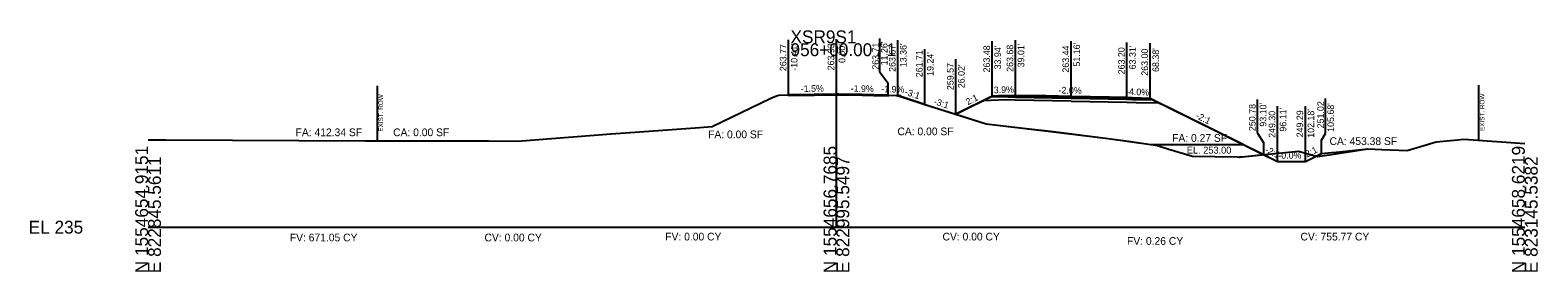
# Model space of a CAD drawing. Extents: x -26 to 823017, y -16 to 1558356.
# Drawn here: x -25.7 to 302.8, y 3990.3 to 4042.8 of the extents above; entities that cross this region are included whole.
import ezdxf

# ---------------------------------------------------------------- set-up
doc = ezdxf.new("R2010")
doc.units = 0
for name, color, linetype in [('ASPHALT_19MM1', 7, 'Continuous'), ('CONST_DCH', 7, 'Continuous'), ('CONST_LV3', 7, 'Continuous'), ('Draft_XS_Grid', 7, 'Continuous'), ('DTM_CORRIDOR', 7, 'Continuous'), ('DTM_P_FINISHED_GRADE2', 7, 'Continuous'), ('DTM_TEMP_DROP', 7, 'Continuous'), ('DTM_X_GROUND', 7, 'Continuous'), ('PROFILES_DCH_2', 7, 'Continuous'), ('XS_CELL', 7, 'Continuous'), ('XS_P_ASPHALT', 7, 'Continuous'), ('XS_P_DR_GRAVEL', 7, 'Continuous'), ('XS_P_GROUND', 7, 'Continuous'), ('XS_P_NULL_POINT', 7, 'Continuous'), ('XS_P_SHOULDER', 7, 'Continuous'), ('XS_P_SUBGRADE_GRANULAR', 7, 'Continuous'), ('XS_P_SUBGRADE_LEVELING', 7, 'Continuous'), ('XS_P_SUBGRADE_MILLING', 7, 'Continuous'), ('XS_P_SUBGRADE_UNDERCUT', 7, 'Continuous'), ('XS_P_TX_CLEARZONE', 7, 'Continuous'), ('XS_P_TX_FS_BS', 7, 'Continuous'), ('XS_SHEET_EW_TX_AREA', 7, 'Continuous'), ('XS_SHEET_EW_TX_VOLUME', 7, 'Continuous'), ('XS_X_ROW', 7, 'Continuous')]:
    doc.layers.add(name, color=color, linetype=linetype)

msp = doc.modelspace()

# ---------------------------------------------------------------- linework, layer by layer
at = {"layer": 'ASPHALT_19MM1'}
msp.add_lwpolyline([(189.01, 4028.31), (201.16, 4028.07), (213.31, 4027.82), (213.31, 4028.03), (201.16, 4028.27), (189.01, 4028.52), (189.01, 4028.31)], dxfattribs=at)
at = {"layer": 'CONST_DCH'}
msp.add_lwpolyline([(189.01, 4028.52), (201.16, 4028.27), (213.31, 4028.03), (213.31, 4028.2), (201.16, 4028.44), (189.01, 4028.68), (189.01, 4028.52)], dxfattribs=at)
at = {"layer": 'CONST_LV3'}
for points in [[(0, 4019.01), (3.88, 4019), (47.41, 4018.78), (74.22, 4018.76), (80.47, 4018.69), (100.92, 4020.33), (111.18, 4021.06), (119.23, 4021.63), (122.89, 4021.89), (125.04, 4022.93), (135.67, 4028.05), (136.96, 4028.54), (137.47, 4028.73), (139.59, 4028.77), (139.59, 4028.77)], [(150, 4028.93), (164, 4028.65)], [(161.26, 4028.71), (161.26, 4028.71), (163.05, 4028.67), (163.25, 4028.61), (164.59, 4028.2), (167.06, 4027.41), (168.85, 4026.84), (176.02, 4024.57), (177.03, 4025.07), (183.94, 4028.48), (185.3, 4028.54), (189.01, 4028.68), (195.69, 4028.55), (201.16, 4028.44), (209.49, 4028.28), (213.31, 4028.2), (214.47, 4028.15), (218.38, 4028), (221.4, 4026.51), (227.94, 4023.28), (228.54, 4022.98), (228.89, 4022.81), (242.42, 4016.12), (246.11, 4014.3), (250.89, 4014.29), (252.18, 4014.29), (254.68, 4015.52), (254.71, 4015.54), (255.35, 4015.86), (255.41, 4015.88), (255.51, 4015.94), (255.68, 4016.02), (257.84, 4016.24), (258.89, 4016.35), (265.78, 4017.02), (265.8, 4017.02), (268.78, 4016.91), (268.81, 4016.91), (274.34, 4016.71), (280.65, 4018.55), (284.58, 4018.95), (286.69, 4019.17), (300, 4018.18)], [(163.36, 4028.67), (163.36, 4028.67), (164, 4028.65)], [(176.02, 4024.57), (177.03, 4025.07), (183.94, 4028.48), (185.3, 4028.54), (189.01, 4028.68)], [(218.38, 4028), (227.94, 4023.28), (233.56, 4020.5), (243.1, 4015.78)]]:
    msp.add_lwpolyline(points, dxfattribs=at)
at = {"layer": 'DTM_P_FINISHED_GRADE2'}
msp.add_lwpolyline([(139.59, 4028.77), (150, 4028.93), (161.26, 4028.71)], dxfattribs=at)
at = {"layer": 'DTM_X_GROUND'}
for points in [[(0, 4019.01), (3.88, 4019), (47.41, 4018.78), (74.22, 4018.76), (80.47, 4018.69), (100.92, 4020.33), (111.18, 4021.06), (119.23, 4021.63), (122.89, 4021.89), (125.04, 4022.93), (135.67, 4028.05), (136.96, 4028.54), (137.47, 4028.73), (145.15, 4028.85), (147.38, 4028.89), (150.53, 4028.94), (155.6, 4028.83), (158.04, 4028.78), (163.05, 4028.67), (163.25, 4028.61), (164.59, 4028.2), (168.85, 4026.84), (182.63, 4022.48), (191.31, 4021.48), (196.62, 4020.86), (209.24, 4019.31), (213.67, 4018.68), (219.99, 4017.79), (222.42, 4016.98), (227.57, 4015.43), (237.29, 4015.27), (237.71, 4015.23), (237.8, 4015.26), (237.89, 4015.29), (237.89, 4015.29), (238.44, 4015.34), (250.68, 4016.51), (254.81, 4015.4), (257.84, 4015.79), (265.78, 4017.02), (265.8, 4017.02), (268.78, 4016.91), (268.81, 4016.91), (274.34, 4016.71), (280.65, 4018.55), (284.58, 4018.95), (286.69, 4019.17), (300, 4018.18)], [(0, 4019.01), (3.88, 4019), (47.41, 4018.78), (74.22, 4018.76), (80.47, 4018.69), (100.92, 4020.33), (111.18, 4021.06), (119.23, 4021.63), (122.89, 4021.89), (125.04, 4022.93), (135.67, 4028.05), (136.96, 4028.54), (137.47, 4028.73), (145.15, 4028.85), (147.38, 4028.89), (150.53, 4028.94), (155.6, 4028.83), (158.04, 4028.78), (163.05, 4028.67), (163.25, 4028.61), (164.59, 4028.2), (167.06, 4027.41), (168.85, 4026.84), (176.02, 4024.57), (177.03, 4025.07), (183.94, 4028.48), (185.3, 4028.54), (189.01, 4028.68), (195.69, 4028.55), (201.16, 4028.44), (209.49, 4028.28), (213.31, 4028.2), (214.47, 4028.15), (218.38, 4028), (221.4, 4026.51), (227.94, 4023.28), (228.54, 4022.98), (228.89, 4022.81), (242.42, 4016.12), (246.11, 4014.3), (250.89, 4014.29), (252.18, 4014.29), (254.68, 4015.52), (254.71, 4015.54), (255.35, 4015.86), (255.41, 4015.88), (255.51, 4015.94), (255.68, 4016.02), (257.84, 4016.24), (258.89, 4016.35), (265.78, 4017.02), (265.8, 4017.02), (268.78, 4016.91), (268.81, 4016.91), (274.34, 4016.71), (280.65, 4018.55), (284.58, 4018.95), (286.69, 4019.17), (300, 4018.18)], [(0, 4019.01), (3.88, 4019), (47.41, 4018.78), (74.22, 4018.76), (80.47, 4018.69), (100.92, 4020.33), (111.18, 4021.06), (119.23, 4021.63), (122.89, 4021.89), (125.04, 4022.93), (135.67, 4028.05), (136.96, 4028.54), (137.47, 4028.73), (139.59, 4028.77), (139.59, 4028.77), (150, 4028.93), (150, 4028.93), (150, 4028.93), (150, 4028.93), (150, 4028.93), (150, 4028.93), (161.26, 4028.71), (161.26, 4028.71), (161.26, 4028.71), (163.05, 4028.67), (163.25, 4028.61), (164.59, 4028.2), (167.06, 4027.41), (168.85, 4026.84), (176.02, 4024.57), (177.03, 4025.07), (183.94, 4028.48), (185.3, 4028.54), (189.01, 4028.68), (195.69, 4028.55), (201.16, 4028.44), (209.49, 4028.28), (213.31, 4028.2), (214.47, 4028.15), (218.38, 4028), (221.4, 4026.51), (227.94, 4023.28), (228.54, 4022.98), (228.89, 4022.81), (242.42, 4016.12), (246.11, 4014.3), (250.89, 4014.29), (252.18, 4014.29), (254.68, 4015.52), (254.71, 4015.54), (255.35, 4015.86), (255.41, 4015.88), (255.51, 4015.94), (255.68, 4016.02), (257.84, 4016.24), (258.89, 4016.35), (265.78, 4017.02), (265.8, 4017.02), (268.78, 4016.91), (268.81, 4016.91), (274.34, 4016.71), (280.65, 4018.55), (284.58, 4018.95), (286.69, 4019.17), (300, 4018.18)]]:
    msp.add_lwpolyline(points, dxfattribs=at)
at = {"layer": 'XS_CELL'}
for p, q in [((150, 4000), (150, 4040)), ((0, 4000), (150, 4000)), ((150, 4000), (300, 4000))]:
    msp.add_line(p, q, dxfattribs=at)
at = {"layer": 'XS_P_ASPHALT'}
msp.add_lwpolyline([(139.59, 4028.77), (150, 4028.93), (150, 4028.93), (161.26, 4028.71), (161.26, 4028.71), (161.26, 4028.59), (161.26, 4028.59), (150, 4028.8), (150, 4028.8), (139.59, 4028.64), (139.59, 4028.77)], dxfattribs=at)
at = {"layer": 'XS_P_DR_GRAVEL'}
for points in [[(185.3, 4028.54), (183.94, 4028.48), (183.83, 4028.43), (183.8, 4028.41), (187.42, 4028.34), (189.01, 4028.31), (189.01, 4028.43), (189.01, 4028.68), (185.3, 4028.54)], [(214.47, 4028.15), (213.31, 4028.2), (213.31, 4028.11), (213.31, 4027.82), (214.59, 4027.8), (218.96, 4027.71), (218.47, 4027.95), (218.38, 4028), (214.47, 4028.15)]]:
    msp.add_lwpolyline(points, dxfattribs=at)
at = {"layer": 'XS_P_GROUND'}
for points in [[(169.24, 4026.71), (163.36, 4028.67), (163.36, 4028.67)], [(183.94, 4028.48), (176.02, 4024.57)], [(218.38, 4028), (227.94, 4023.28), (228.89, 4022.81), (246.11, 4014.3), (252.18, 4014.29), (255.68, 4016.02)], [(169.24, 4026.71), (169.24, 4026.71), (182.63, 4022.48), (182.63, 4022.48), (182.63, 4022.48), (191.31, 4021.48), (191.31, 4021.48), (196.62, 4020.86), (196.62, 4020.86), (209.24, 4019.31), (213.67, 4018.68), (219.99, 4017.79), (219.99, 4017.79), (222.42, 4016.98), (222.42, 4016.98), (227.57, 4015.43), (227.57, 4015.43), (227.57, 4015.43), (237.29, 4015.27), (237.29, 4015.27), (237.71, 4015.23), (237.8, 4015.26), (237.89, 4015.29), (237.89, 4015.29), (238.44, 4015.34), (238.44, 4015.34), (243.1, 4015.78), (243.1, 4015.78)], [(169.24, 4026.71), (169.24, 4026.71), (182.63, 4022.48), (182.63, 4022.48), (182.63, 4022.48), (191.31, 4021.48), (191.31, 4021.48), (196.62, 4020.86), (196.62, 4020.86), (209.24, 4019.31), (213.67, 4018.68), (219.99, 4017.79), (219.99, 4017.79), (222.42, 4016.98), (222.42, 4016.98), (227.57, 4015.43), (227.57, 4015.43), (227.57, 4015.43), (237.29, 4015.27), (237.29, 4015.27), (237.71, 4015.23), (237.8, 4015.26), (237.89, 4015.29), (237.89, 4015.29), (238.44, 4015.34), (238.44, 4015.34), (243.1, 4015.78), (243.1, 4015.78)]]:
    msp.add_lwpolyline(points, dxfattribs=at)
at = {"layer": 'XS_P_SHOULDER'}
for points in [[(183.94, 4028.48), (185.3, 4028.54), (189.01, 4028.68)], [(218.38, 4028), (214.47, 4028.15), (213.31, 4028.2)]]:
    msp.add_lwpolyline(points, dxfattribs=at)
at = {"layer": 'XS_P_SUBGRADE_GRANULAR'}
for points in [[(189.01, 4027.64), (186.98, 4027.68), (181.92, 4027.48)], [(201.16, 4027.4), (189.01, 4027.64)], [(201.16, 4027.4), (213.31, 4027.16)], [(213.31, 4027.16), (215.34, 4027.12), (220.36, 4027.02)]]:
    msp.add_lwpolyline(points, dxfattribs=at)
at = {"layer": 'XS_P_SUBGRADE_LEVELING'}
for points in [[(161.26, 4028.59), (158.04, 4028.65), (158.04, 4028.65), (155.6, 4028.7), (150.53, 4028.79), (150.53, 4028.79), (150, 4028.8), (150, 4028.8), (147.38, 4028.76), (147.38, 4028.76), (145.15, 4028.73), (139.59, 4028.64), (139.59, 4028.64)], [(139.59, 4028.64), (139.59, 4028.64), (145.15, 4028.73), (147.38, 4028.76), (147.38, 4028.76), (150, 4028.8), (150, 4028.8), (150.53, 4028.79), (150.53, 4028.79), (155.6, 4028.7), (158.04, 4028.65), (158.04, 4028.65), (161.26, 4028.59)]]:
    msp.add_lwpolyline(points, dxfattribs=at)
at = {"layer": 'XS_P_SUBGRADE_MILLING'}
msp.add_lwpolyline([(158.04, 4028.78), (155.6, 4028.83), (150.53, 4028.94), (150.53, 4028.94), (150, 4028.93), (150, 4028.93), (147.38, 4028.89), (147.38, 4028.89), (145.15, 4028.85), (139.59, 4028.77), (139.59, 4028.77), (139.59, 4028.64), (139.59, 4028.64), (145.15, 4028.73), (147.38, 4028.76), (147.38, 4028.76), (150, 4028.8), (150, 4028.8), (150.53, 4028.79), (150.53, 4028.79), (155.6, 4028.7), (158.04, 4028.65), (158.04, 4028.65), (161.26, 4028.59), (161.26, 4028.71), (158.04, 4028.78), (158.04, 4028.78)], dxfattribs=at)
at = {"layer": 'XS_P_SUBGRADE_UNDERCUT'}
msp.add_lwpolyline([(176.02, 4024.57), (182.63, 4022.48), (191.21, 4021.49), (196.72, 4020.84), (209.24, 4019.31), (218.51, 4018), (226.54, 4018), (232.25, 4018), (234.16, 4018), (235.9, 4018), (238.61, 4018), (218.38, 4028), (214.47, 4028.15), (209.49, 4028.28), (201.16, 4028.44), (195.69, 4028.55), (189.01, 4028.68), (183.94, 4028.48)], close=True, dxfattribs=at)
at = {"layer": 'XS_P_TX_CLEARZONE'}
for p, q in [((159.48, 4033.69), (159.48, 4041.05)), ((139.59, 4028.77), (139.59, 4040.77)), ((150, 4028.93), (150, 4040.93)), ((163.36, 4028.67), (163.36, 4040.67)), ((169.24, 4026.71), (169.24, 4038.71)), ((183.94, 4028.48), (183.94, 4040.48)), ((189.01, 4028.68), (189.01, 4040.68)), ((201.16, 4028.44), (201.16, 4040.44)), ((213.31, 4028.2), (213.31, 4040.2)), ((218.38, 4028), (218.38, 4040)), ((176.02, 4024.57), (176.02, 4036.57)), ((159.48, 4033.69), (161.26, 4031.35)), ((161.26, 4028.71), (161.26, 4031.35)), ((256.57, 4020.38), (256.57, 4028.02)), ((241.73, 4020.42), (241.73, 4027.78)), ((246.11, 4014.3), (246.11, 4026.3)), ((252.18, 4014.29), (252.18, 4026.29)), ((241.73, 4020.42), (243.1, 4018.3)), ((243.1, 4015.78), (243.1, 4018.3)), ((255.68, 4018.92), (256.57, 4020.38)), ((255.68, 4016.02), (255.68, 4018.92))]:
    msp.add_line(p, q, dxfattribs=at)
at = {"layer": 'XS_X_ROW'}
for p, q in [((50, 4018.78), (50, 4030.78)), ((290, 4018.92), (290, 4030.92))]:
    msp.add_line(p, q, dxfattribs=at)

# ---------------------------------------------------------------- texts
at = {"layer": 'CONST_DCH'}
for p in [(175.94, 4024.45), (243.03, 4015.66), (246.03, 4014.18)]:
    msp.add_text('X', height=0.24, dxfattribs=at).set_placement(p)
at = {"layer": 'Draft_XS_Grid'}
msp.add_text('-', height=0.0001, dxfattribs=at).set_placement((0, 4000))
at = {"layer": 'DTM_CORRIDOR'}
for p in [(188.93, 4028.56), (201.08, 4028.32), (213.24, 4028.08)]:
    msp.add_text('X', height=0.24, dxfattribs=at).set_placement(p)
at = {"layer": 'DTM_TEMP_DROP'}
for p in [(139.51, 4028.65), (149.92, 4028.81), (161.18, 4028.59)]:
    msp.add_text('X', height=0.24, dxfattribs=at).set_placement(p)
at = {"layer": 'PROFILES_DCH_2'}
for p in [(163.28, 4028.55), (169.16, 4026.59), (243.03, 4015.66)]:
    msp.add_text('X', height=0.24, dxfattribs=at).set_placement(p)
at = {"layer": 'XS_CELL'}
for s, p in [('XSR9S1', (140, 4040)), ('956+00.00 / 1', (140, 4037.2)), ('EL 235', (-26, 3998.6))]:
    msp.add_text(s, height=2.8, dxfattribs=at).set_placement(p)
for s, p in [('N 1554654.9151', (0, 3990)), ('E 822845.5611', (2.8, 3990)), ('N 1554656.7685', (150, 3990)), ('E 822995.5497', (152.8, 3990)), ('N 1554658.6219', (300, 3990)), ('E 823145.5382', (302.8, 3990))]:
    msp.add_text(s, height=2.8, rotation=90, dxfattribs=at).set_placement(p)
at = {"layer": 'XS_P_ASPHALT'}
for p in [(175.94, 4024.45), (255.6, 4015.9)]:
    msp.add_text('X', height=0.24, dxfattribs=at).set_placement(p)
at = {"layer": 'XS_P_NULL_POINT'}
msp.add_text('X', height=0.24, dxfattribs=at).set_placement((252.11, 4014.17))
at = {"layer": 'XS_P_SHOULDER'}
for p in [(183.87, 4028.36), (218.3, 4027.88)]:
    msp.add_text('X', height=0.24, dxfattribs=at).set_placement(p)
at = {"layer": 'XS_P_SUBGRADE_UNDERCUT'}
msp.add_text('EL. 253.00', height=1.5, dxfattribs=at).set_placement((226.35, 4016.01))
at = {"layer": 'XS_P_TX_CLEARZONE'}
for s, p in [('263.77', (139.11, 4033.94)), ("-10.41'", (141.51, 4034.03)), ('263.93', (149.52, 4034.11)), ("0.00'", (151.92, 4035.72)), ('263.71', (159.25, 4034.25)), ("11.26'", (161.13, 4035.2)), ('263.67', (162.88, 4033.78)), ("13.36'", (165.28, 4034.8)), ('261.71', (168.76, 4032.62)), ("19.24'", (171.16, 4032.91)), ('263.48', (183.46, 4033.66)), ("33.94'", (185.86, 4034.32)), ('263.68', (188.53, 4033.79)), ("39.01'", (190.93, 4034.77)), ('263.44', (200.68, 4033.62)), ("51.16'", (203.08, 4034.93)), ('263.20', (212.83, 4033.25)), ("63.31'", (215.23, 4034.33)), ('263.00', (217.9, 4032.94)), ("68.38'", (220.3, 4033.77)), ('259.57', (175.54, 4029.82)), ("26.02'", (177.94, 4030.23)), ('250.78', (241.33, 4020.91)), ("93.10'", (243.68, 4021.87)), ('249.30', (245.63, 4019.42)), ("96.11'", (248.03, 4020.79)), ('249.29', (251.7, 4019.53)), ("102.18'", (254.1, 4019.45)), ('251.02', (256.22, 4021.51)), ("105.68'", (258.42, 4020.74))]:
    msp.add_text(s, height=1.44, rotation=90, dxfattribs=at).set_placement(p)
at = {"layer": 'XS_P_TX_FS_BS'}
for s, rotation, p in [('-1.5%', 0.8865, (142.23, 4029.41)), ('-1.9%', 358.9041, (153.09, 4029.47)), ('-1.9%', 358.9348, (159.77, 4029.34)), ('-3:1', 341.5651, (164.77, 4028.84)), ('-3:1', 342.4811, (171.08, 4026.76)), ('2:1', 26.2716, (178.62, 4026.52)), ('3.9%', 2.2562, (184.31, 4029.1)), ('-2.0%', 358.8631, (198.38, 4029.1)), ('-4.0%', 357.7327, (213.08, 4028.81)), ('-2:1', 333.7056, (228.15, 4023.78)), ('-2:1', 333.6952, (243.25, 4016.38)), ('-0.0%', 359.9724, (246.3, 4014.9)), ('2:1', 26.26, (252.57, 4015.15))]:
    msp.add_text(s, height=1.44, rotation=rotation, dxfattribs=at).set_placement(p)
at = {"layer": 'XS_SHEET_EW_TX_AREA'}
for s, p in [('FA: 412.34 SF', (32.15, 4019.8)), ('CA: 0.00 SF', (53.4, 4019.8)), ('CA: 0.00 SF', (163.29, 4020)), ('FA: 0.00 SF', (122.03, 4019.35)), ('FA: 0.27 SF', (223.14, 4018.57)), ('CA: 453.38 SF', (257.45, 4017.88))]:
    msp.add_text(s, height=1.68, dxfattribs=at).set_placement(p)
at = {"layer": 'XS_SHEET_EW_TX_VOLUME'}
for s, p in [('FV: 671.05 CY', (30.89, 3996.92)), ('CV: 0.00 CY', (73.31, 3996.92)), ('FV: 0.00 CY', (112.7, 3997.12)), ('CV: 0.00 CY', (173.12, 3997.12)), ('CV: 755.77 CY', (251.12, 3997.12)), ('FV: 0.26 CY', (213.32, 3996.17))]:
    msp.add_text(s, height=1.68, dxfattribs=at).set_placement(p)
at = {"layer": 'XS_X_ROW'}
for p in [(51.2, 4020.78), (291.2, 4020.92)]:
    msp.add_text('EXIST. ROW', height=1, rotation=90, dxfattribs=at).set_placement(p)

doc.saveas('drawing.dxf')
